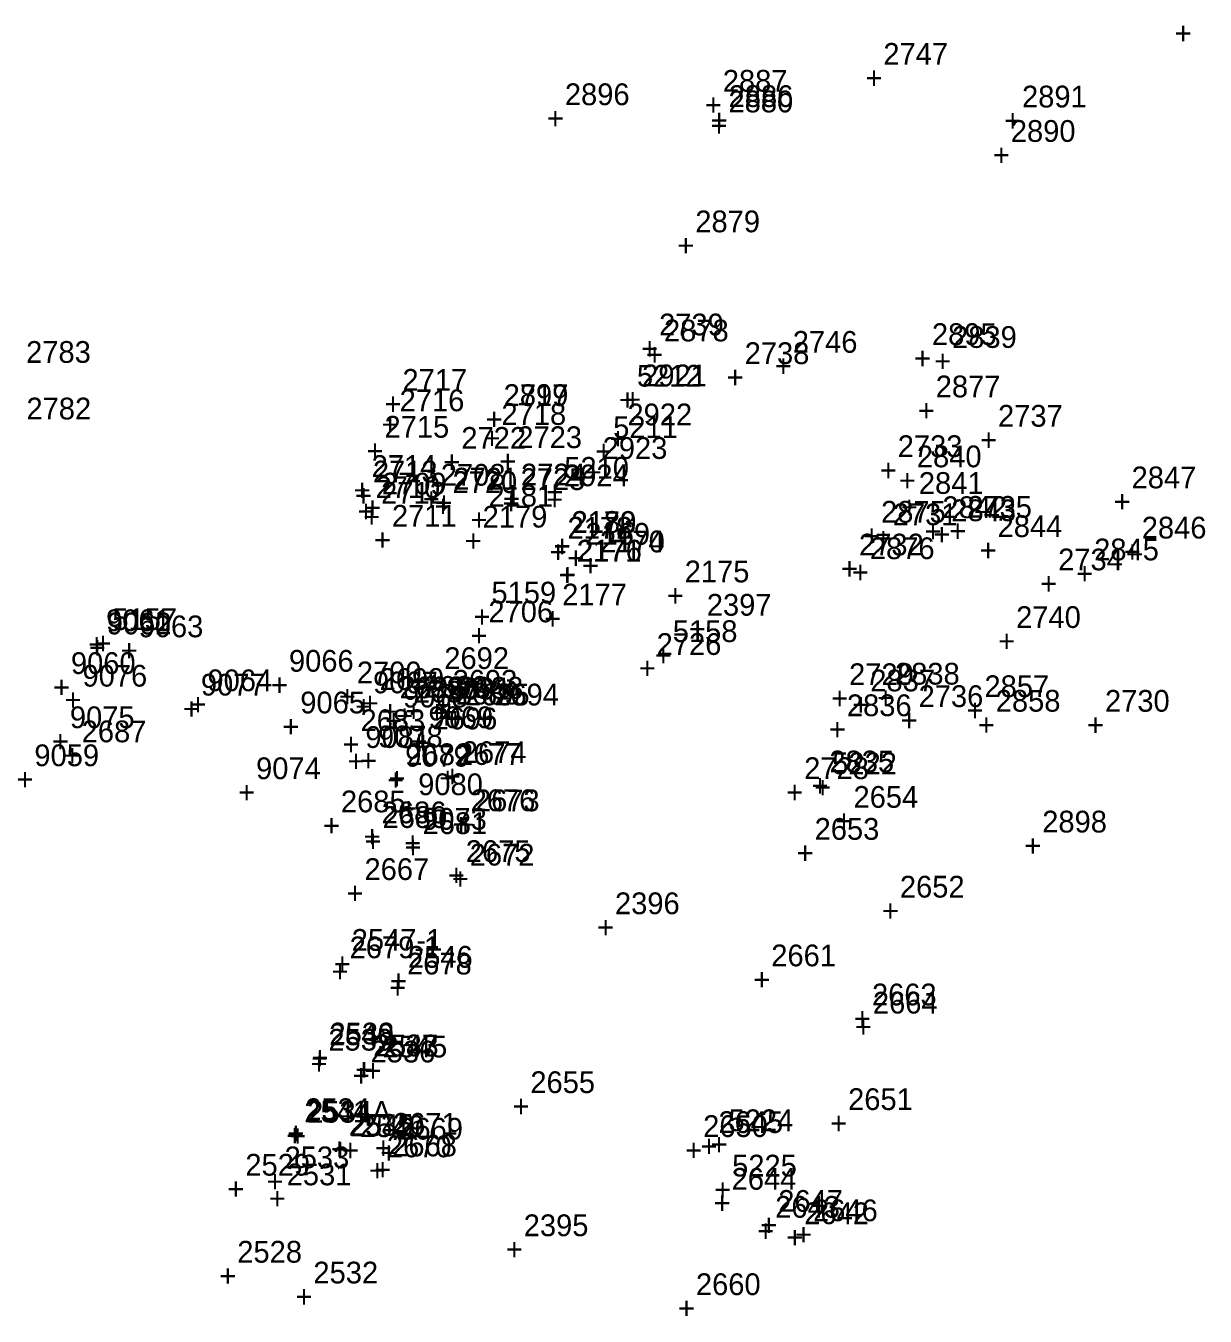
# Model space of a CAD drawing. Extents: x 1136220 to 1137808, y 528804 to 531215.
# Drawn here: x 1136907.4 to 1137043, y 529478.8 to 529627.1 of the extents above; entities that cross this region are included whole.
import ezdxf

# ---------------------------------------------------------------- set-up
doc = ezdxf.new("R2010")
doc.units = 0
for name, color, linetype in [('S_Buildings', 7, 'Continuous'), ('S_Buildings_Attachments', 7, 'Continuous'), ('S_Buildings_SillElevation', 7, 'Continuous'), ('S_Buildings_Steps_Brick', 7, 'Continuous'), ('S_Curb_Type_1', 7, 'Continuous'), ('S_Curb_Type_3', 7, 'Continuous'), ('S_Drainage_CB', 7, 'Continuous'), ('S_Drainage_Culvert_Top', 7, 'Continuous'), ('S_Drainage_Invert', 7, 'Continuous'), ('S_Drainage_Sump', 7, 'Continuous'), ('S_Ground_Elevation', 7, 'Continuous'), ('S_Ground_SpotElevation', 7, 'Continuous'), ('S_Misc_MiscItems', 7, 'Continuous'), ('S_Property_Walkways', 7, 'Continuous'), ('S_Roadway_Centerline', 7, 'Continuous'), ('S_Roadway_Drive_Paved', 7, 'Continuous'), ('S_Roadway_Edge_Pavement', 7, 'Continuous'), ('S_Roadway_Sidewalks', 7, 'Continuous'), ('S_Traffic_Sign_SinglePost', 7, 'Continuous'), ('S_Utilities_Gas_Gate', 7, 'Continuous'), ('S_Utilities_GuyWire3', 7, 'Continuous'), ('S_Utilities_Hydrant', 7, 'Continuous'), ('S_Utilities_Pole_Joint', 7, 'Continuous'), ('S_Utilities_UG_Gas_Line', 7, 'Continuous'), ('S_Utilities_UG_Sanitary_MH', 7, 'Continuous'), ('S_Utilities_UG_Water_Gate', 7, 'Continuous'), ('S_Utilities_UG_Water_Line', 7, 'Continuous')]:
    doc.layers.add(name, color=color, linetype=linetype)

msp = doc.modelspace()

# ---------------------------------------------------------------- texts
at = {"layer": 'S_Buildings'}
for s, p in [('+', (1137039.47, 529624.97)), ('2896', (1136969.39, 529617.95)), ('+', (1136967.33, 529615.2)), ('2719', (1136962.35, 529583.37)), ('2897', (1136962.35, 529583.38)), ('+', (1136960.29, 529580.63)), ('+', (1136960.28, 529580.62)), ('2687', (1136913.86, 529544.72)), ('+', (1136911.8, 529541.97)), ('2686', (1136948.33, 529535.41)), ('+', (1136946.27, 529532.66)), ('2652', (1137007.89, 529526.87)), ('+', (1137005.83, 529524.12)), ('2651', (1137001.94, 529502.45)), ('+', (1136999.88, 529499.7)), ('2533', (1136937.17, 529495.76)), ('+', (1136935.11, 529493.01))]:
    msp.add_text(s, height=2.5, dxfattribs=at).set_placement(p)
at = {"layer": 'S_Buildings_Attachments'}
for s, p in [('2547-1', (1136944.89, 529520.75)), ('2546', (1136951.36, 529518.81)), ('+', (1136942.83, 529518)), ('+', (1136949.29, 529516.06)), ('2545', (1136948.43, 529508.49)), ('+', (1136946.37, 529505.74))]:
    msp.add_text(s, height=2.5, dxfattribs=at).set_placement(p)
at = {"layer": 'S_Buildings_SillElevation'}
for s, p in [('2667', (1136946.36, 529528.89)), ('+', (1136944.29, 529526.14)), ('2664', (1137004.79, 529513.54)), ('+', (1137002.72, 529510.79))]:
    msp.add_text(s, height=2.5, dxfattribs=at).set_placement(p)
at = {"layer": 'S_Buildings_Steps_Brick'}
for s, p in [('2538', (1136942.34, 529509.99)), ('2539', (1136942.21, 529509.28)), ('2537', (1136947.37, 529508.63)), ('+', (1136940.28, 529507.24)), ('2536', (1136947.06, 529507.92)), ('+', (1136940.15, 529506.53)), ('+', (1136945.31, 529505.88)), ('+', (1136945, 529505.17)), ('2534', (1136939.55, 529501.29)), ('2534A', (1136939.77, 529501)), ('2535', (1136944.55, 529499.49)), ('+', (1136937.49, 529498.54)), ('+', (1136937.71, 529498.25)), ('+', (1136942.49, 529496.74))]:
    msp.add_text(s, height=2.5, dxfattribs=at).set_placement(p)
at = {"layer": 'S_Curb_Type_1'}
for s, p in [('5212', (1136977.67, 529585.6)), ('+', (1136975.61, 529582.85)), ('5211', (1136974.94, 529579.69)), ('+', (1136972.87, 529576.94)), ('2714', (1136947.18, 529575.22)), ('5210', (1136969.32, 529575.01)), ('2721', (1136956.57, 529573.77)), ('2724', (1136964.34, 529574.24)), ('+', (1136945.12, 529572.47)), ('+', (1136967.26, 529572.26)), ('+', (1136954.51, 529571.02)), ('+', (1136962.28, 529571.49))]:
    msp.add_text(s, height=2.5, dxfattribs=at).set_placement(p)
at = {"layer": 'S_Curb_Type_3'}
for s, p in [('9062', (1136916.74, 529557.12)), ('9063', (1136920.4, 529556.79)), ('+', (1136914.68, 529554.37)), ('+', (1136918.34, 529554.04)), ('9066', (1136937.68, 529552.83)), ('+', (1136935.62, 529550.08)), ('9067', (1136947.35, 529550.35)), ('9068', (1136950.79, 529548.72)), ('+', (1136945.29, 529547.6)), ('+', (1136948.73, 529545.97)), ('9069', (1136953.71, 529546.34)), ('+', (1136951.65, 529543.59)), ('2677', (1136957, 529542.12)), ('5222', (1137000.11, 529541.05)), ('+', (1136954.94, 529539.37)), ('+', (1136998.05, 529538.3)), ('2676', (1136958.56, 529536.8)), ('+', (1136956.5, 529534.05)), ('2675', (1136958, 529530.96)), ('+', (1136955.94, 529528.21)), ('2671', (1136949.63, 529499.61)), ('5224', (1136988.2, 529500.02)), ('+', (1136947.56, 529496.86)), ('2670', (1136948.93, 529497.02)), ('+', (1136986.14, 529497.27)), ('5225', (1136988.61, 529494.81)), ('+', (1136946.87, 529494.27)), ('+', (1136986.55, 529492.06)), ('2647', (1136993.91, 529490.75)), ('2646', (1136997.91, 529489.67)), ('+', (1136991.85, 529488)), ('+', (1136995.84, 529486.92))]:
    msp.add_text(s, height=2.5, dxfattribs=at).set_placement(p)
at = {"layer": 'S_Drainage_CB'}
for s, p in [('2709', (1136948.36, 529573.2)), ('+', (1136946.3, 529570.45)), ('2688', (1136957.17, 529549.73)), ('+', (1136955.11, 529546.98))]:
    msp.add_text(s, height=2.5, dxfattribs=at).set_placement(p)
at = {"layer": 'S_Drainage_Culvert_Top'}
for s, p in [('2181', (1136960.61, 529571.81)), ('2711', (1136949.51, 529569.5)), ('2179', (1136959.94, 529569.4)), ('2180', (1136970.16, 529568.79)), ('+', (1136958.55, 529569.06)), ('2178', (1136969.68, 529568.11)), ('+', (1136947.45, 529566.75)), ('+', (1136957.88, 529566.65)), ('2174', (1136973.42, 529566.55)), ('+', (1136967.62, 529565.36)), ('+', (1136968.1, 529566.04)), ('2176', (1136970.8, 529565.5)), ('+', (1136971.36, 529563.8)), ('2175', (1136983.16, 529563.1)), ('+', (1136968.74, 529562.75)), ('2177', (1136969.08, 529560.45)), ('+', (1136981.1, 529560.35)), ('+', (1136967.01, 529557.7)), ('2692', (1136955.53, 529553.14)), ('2690', (1136953.1, 529549.83)), ('+', (1136953.47, 529550.39)), ('2694', (1136961.27, 529548.95)), ('+', (1136951.04, 529547.08)), ('+', (1136959.21, 529546.2))]:
    msp.add_text(s, height=2.5, dxfattribs=at).set_placement(p)
at = {"layer": 'S_Drainage_Invert'}
for s, p in [('2712', (1136948.27, 529572.15)), ('+', (1136946.21, 529569.4)), ('2173', (1136970.14, 529568.76)), ('2172', (1136969.72, 529568.13)), ('2170', (1136973.44, 529566.55)), ('+', (1136967.66, 529565.38)), ('+', (1136968.08, 529566.01)), ('2171', (1136970.74, 529565.46)), ('+', (1136971.38, 529563.8)), ('+', (1136968.68, 529562.71)), ('2691', (1136955.78, 529549.63)), ('2693', (1136956.49, 529550.54)), ('2695', (1136957.89, 529548.96)), ('+', (1136954.43, 529547.79)), ('+', (1136953.72, 529546.88)), ('+', (1136955.83, 529546.21))]:
    msp.add_text(s, height=2.5, dxfattribs=at).set_placement(p)
at = {"layer": 'S_Drainage_Sump'}
for s, p in [('2710', (1136947.63, 529572.78)), ('+', (1136945.57, 529570.03)), ('2689', (1136956.85, 529549.06)), ('+', (1136954.79, 529546.31))]:
    msp.add_text(s, height=2.5, dxfattribs=at).set_placement(p)
at = {"layer": 'S_Ground_Elevation'}
for s, p in [('2887', (1136987.54, 529619.5)), ('2886', (1136988.21, 529617.74)), ('+', (1136985.48, 529616.75)), ('+', (1136986.15, 529614.99)), ('9076', (1136913.95, 529551.12)), ('9077', (1136927.56, 529550.09)), ('+', (1136911.89, 529548.37)), ('+', (1136925.5, 529547.34)), ('9075', (1136912.5, 529546.34)), ('9078', (1136947.91, 529544.14)), ('+', (1136910.44, 529543.59)), ('+', (1136945.84, 529541.39)), ('9079', (1136951.03, 529541.92)), ('9074', (1136933.9, 529540.48)), ('+', (1136948.97, 529539.17)), ('9080', (1136952.53, 529538.64)), ('+', (1136931.84, 529537.73)), ('+', (1136950.47, 529535.89)), ('9073', (1136952.98, 529534.67)), ('+', (1136950.92, 529531.92)), ('2540', (1136942.29, 529509.9)), ('2543', (1136947.44, 529508.62)), ('+', (1136940.23, 529507.15)), ('+', (1136945.38, 529505.87)), ('2541', (1136939.44, 529501.04)), ('2542', (1136944.67, 529499.44)), ('+', (1136937.38, 529498.29)), ('+', (1136942.61, 529496.69))]:
    msp.add_text(s, height=2.5, dxfattribs=at).set_placement(p)
at = {"layer": 'S_Ground_SpotElevation'}
for s, p in [('2717', (1136950.72, 529585.12)), ('2716', (1136950.4, 529582.77)), ('+', (1136948.66, 529582.37)), ('2718', (1136962.1, 529581.2)), ('+', (1136948.34, 529580.02)), ('+', (1136960.04, 529578.45)), ('2685', (1136943.65, 529536.67)), ('+', (1136941.59, 529533.92)), ('2663', (1137004.68, 529514.48)), ('+', (1137002.61, 529511.73)), ('2660', (1136984.45, 529481.18)), ('+', (1136982.39, 529478.44))]:
    msp.add_text(s, height=2.5, dxfattribs=at).set_placement(p)
at = {"layer": 'S_Misc_MiscItems'}
for s, p in [('2898', (1137024.25, 529534.35)), ('+', (1137022.19, 529531.6))]:
    msp.add_text(s, height=2.5, dxfattribs=at).set_placement(p)
at = {"layer": 'S_Property_Walkways'}
for s, p in [('2715', (1136948.66, 529579.73)), ('2722', (1136957.49, 529578.45)), ('2723', (1136963.92, 529578.53)), ('+', (1136946.6, 529576.98)), ('+', (1136955.42, 529575.7)), ('+', (1136961.86, 529575.78)), ('2683', (1136945.9, 529546)), ('+', (1136943.84, 529543.25)), ('2682', (1136951.18, 529542.09)), ('+', (1136949.12, 529539.34)), ('2680', (1136948.43, 529534.87)), ('2681', (1136953.03, 529534.17)), ('+', (1136946.37, 529532.12)), ('+', (1136950.96, 529531.42)), ('2679-1', (1136944.65, 529519.9)), ('2678', (1136951.25, 529518.03)), ('+', (1136942.58, 529517.15)), ('+', (1136949.19, 529515.28)), ('2549', (1136945.83, 529499.34)), ('+', (1136943.77, 529496.59))]:
    msp.add_text(s, height=2.5, dxfattribs=at).set_placement(p)
at = {"layer": 'S_Roadway_Centerline'}
for s, p in [('2747', (1137005.99, 529622.59)), ('+', (1137003.93, 529619.84)), ('2746', (1136995.58, 529589.49)), ('+', (1136993.51, 529586.74)), ('5159', (1136960.95, 529560.67)), ('2397', (1136985.7, 529559.27)), ('+', (1136958.89, 529557.92)), ('2740', (1137021.25, 529557.86)), ('5158', (1136981.79, 529556.24)), ('+', (1136983.64, 529556.52)), ('+', (1137019.19, 529555.11)), ('+', (1136979.73, 529553.49)), ('2396', (1136975.15, 529524.96)), ('+', (1136973.09, 529522.21)), ('2395', (1136964.66, 529487.95)), ('+', (1136962.6, 529485.2))]:
    msp.add_text(s, height=2.5, dxfattribs=at).set_placement(p)
at = {"layer": 'S_Roadway_Drive_Paved'}
for s, p in [('9061', (1136916.66, 529557.49)), ('+', (1136914.6, 529554.74)), ('9060', (1136912.62, 529552.57)), ('+', (1136910.56, 529549.82)), ('9059', (1136908.42, 529541.97)), ('+', (1136906.36, 529539.22)), ('2529', (1136932.67, 529494.91)), ('2531', (1136937.42, 529493.8)), ('+', (1136930.6, 529492.16)), ('+', (1136935.36, 529491.05)), ('2528', (1136931.74, 529484.91)), ('+', (1136929.68, 529482.16)), ('2532', (1136940.49, 529482.52)), ('+', (1136938.43, 529479.77))]:
    msp.add_text(s, height=2.5, dxfattribs=at).set_placement(p)
at = {"layer": 'S_Roadway_Edge_Pavement'}
for s, p in [('2891', (1137021.93, 529617.69)), ('2880', (1136988.19, 529617.12)), ('+', (1136986.13, 529614.37)), ('+', (1137019.87, 529614.94)), ('2890', (1137020.64, 529613.73)), ('+', (1137018.58, 529610.98)), ('2879', (1136984.38, 529603.34)), ('+', (1136982.32, 529600.59)), ('2878', (1136980.78, 529590.8)), ('2839', (1137013.89, 529590.05)), ('+', (1136978.72, 529588.05)), ('+', (1137011.83, 529587.3)), ('2921', (1136978.27, 529585.64)), ('2877', (1137012.01, 529584.37)), ('+', (1136976.21, 529582.89)), ('2922', (1136976.58, 529581.15)), ('+', (1137009.95, 529581.62)), ('+', (1136974.52, 529578.4)), ('2923', (1136973.73, 529577.29)), ('2840', (1137009.84, 529576.33)), ('2713', (1136947.33, 529574.59)), ('2720', (1136956.47, 529573.37)), ('2725', (1136964.3, 529573.71)), ('2924', (1136969.29, 529574.15)), ('+', (1136971.67, 529574.54)), ('2841', (1137010.07, 529573.27)), ('2847', (1137034.52, 529573.91)), ('+', (1137007.78, 529573.58)), ('+', (1136945.27, 529571.84)), ('+', (1136962.24, 529570.96)), ('+', (1136967.23, 529571.4)), ('2842', (1137012.78, 529570.49)), ('+', (1137032.46, 529571.16)), ('+', (1136954.41, 529570.62)), ('+', (1137008.01, 529570.52)), ('2843', (1137013.8, 529570.13)), ('+', (1137010.71, 529567.74)), ('2844', (1137019.12, 529568.31)), ('2846', (1137035.69, 529568.14)), ('+', (1137011.74, 529567.38)), ('+', (1137017.06, 529565.56)), ('2845', (1137030.22, 529565.63)), ('+', (1137033.63, 529565.39)), ('+', (1137028.16, 529562.88)), ('5157', (1136917.38, 529557.62)), ('+', (1136915.32, 529554.87)), ('2700', (1136945.48, 529551.5)), ('2838', (1137007.33, 529551.35)), ('2699', (1136948.09, 529550.74)), ('2698', (1136950.4, 529549.78)), ('2837', (1137004.49, 529550.57)), ('+', (1136943.42, 529548.75)), ('2697', (1136952.06, 529549.28)), ('+', (1137005.27, 529548.6)), ('2858', (1137018.91, 529548.24)), ('+', (1136946.03, 529547.99)), ('+', (1136948.34, 529547.03)), ('2836', (1137001.8, 529547.72)), ('+', (1137002.43, 529547.82)), ('+', (1136950, 529546.53)), ('2696', (1136954.19, 529546.2)), ('+', (1137016.85, 529545.49)), ('+', (1136999.74, 529544.97)), ('+', (1136952.13, 529543.45)), ('2674', (1136957.54, 529542.33)), ('2835', (1136999.79, 529541.26)), ('+', (1136955.48, 529539.58)), ('+', (1136997.73, 529538.51)), ('2673', (1136959.05, 529536.79)), ('+', (1136956.99, 529534.04)), ('2672', (1136958.46, 529530.55)), ('+', (1136956.4, 529527.8)), ('2661', (1136993.11, 529518.97)), ('+', (1136991.05, 529516.22)), ('2669', (1136950.24, 529499.05)), ('2645', (1136987.04, 529499.81)), ('2668', (1136949.54, 529497.13)), ('+', (1136984.98, 529497.06)), ('+', (1136948.18, 529496.3)), ('+', (1136947.48, 529494.38)), ('2644', (1136988.55, 529493.29)), ('+', (1136986.49, 529490.54)), ('2643', (1136993.56, 529490.07)), ('2642', (1136996.9, 529489.33)), ('+', (1136991.5, 529487.32)), ('+', (1136994.84, 529486.58))]:
    msp.add_text(s, height=2.5, dxfattribs=at).set_placement(p)
at = {"layer": 'S_Roadway_Sidewalks'}
for s, p in [('9064', (1136928.31, 529550.59)), ('9065', (1136938.98, 529548.04)), ('+', (1136926.25, 529547.84)), ('+', (1136936.92, 529545.3))]:
    msp.add_text(s, height=2.5, dxfattribs=at).set_placement(p)
at = {"layer": 'S_Traffic_Sign_SinglePost'}
for s, p in [('2739', (1136980.22, 529591.49)), ('+', (1136978.15, 529588.74)), ('2735', (1137015.63, 529570.52)), ('+', (1137013.57, 529567.77)), ('2736', (1137010.04, 529548.77)), ('+', (1137007.98, 529546.02)), ('9081', (1136946.46, 529544.07)), ('+', (1136944.4, 529541.32)), ('2653', (1136998.09, 529533.51)), ('+', (1136996.03, 529530.76))]:
    msp.add_text(s, height=2.5, dxfattribs=at).set_placement(p)
at = {"layer": 'S_Utilities_Gas_Gate'}
for s, p in [('2731', (1137007.07, 529569.67)), ('2732', (1137003.19, 529566.19)), ('+', (1137005.01, 529566.92)), ('+', (1137001.13, 529563.44)), ('2650', (1136985.28, 529499.35)), ('+', (1136983.22, 529496.6))]:
    msp.add_text(s, height=2.5, dxfattribs=at).set_placement(p)
at = {"layer": 'S_Utilities_GuyWire3'}
msp.add_text('2783', height=2.5, dxfattribs=at).set_placement((1136907.47, 529588.33))
at = {"layer": 'S_Utilities_Hydrant'}
for s, p in [('2737', (1137019.17, 529580.99)), ('+', (1137017.11, 529578.24))]:
    msp.add_text(s, height=2.5, dxfattribs=at).set_placement(p)
at = {"layer": 'S_Utilities_Pole_Joint'}
for s, p in [('2782', (1136907.51, 529581.83)), ('2654', (1137002.56, 529537.19)), ('+', (1137000.5, 529534.44))]:
    msp.add_text(s, height=2.5, dxfattribs=at).set_placement(p)
at = {"layer": 'S_Utilities_UG_Gas_Line'}
for s, p in [('2895', (1137011.57, 529590.38)), ('+', (1137009.51, 529587.63)), ('2733', (1137007.64, 529577.5)), ('+', (1137005.58, 529574.75)), ('2875', (1137005.73, 529569.96)), ('+', (1137003.67, 529567.21)), ('2876', (1137004.44, 529565.77)), ('2734', (1137026.08, 529564.48)), ('+', (1137002.38, 529563.02)), ('+', (1137024.02, 529561.73)), ('2728', (1136996.89, 529540.49)), ('+', (1136994.83, 529537.74))]:
    msp.add_text(s, height=2.5, dxfattribs=at).set_placement(p)
at = {"layer": 'S_Utilities_UG_Sanitary_MH'}
for s, p in [('2169', (1136971.74, 529567.43)), ('+', (1136969.67, 529564.68))]:
    msp.add_text(s, height=2.5, dxfattribs=at).set_placement(p)
at = {"layer": 'S_Utilities_UG_Water_Gate'}
for s, p in [('2738', (1136990.05, 529588.19)), ('+', (1136987.99, 529585.44)), ('2708', (1136955.13, 529574.21)), ('+', (1136953.07, 529571.46)), ('2706', (1136960.6, 529558.51)), ('+', (1136958.54, 529555.76)), ('2655', (1136965.42, 529504.4)), ('+', (1136963.36, 529501.65))]:
    msp.add_text(s, height=2.5, dxfattribs=at).set_placement(p)
at = {"layer": 'S_Utilities_UG_Water_Line'}
for s, p in [('2726', (1136979.94, 529554.76)), ('+', (1136977.88, 529552.01)), ('2729', (1137002.05, 529551.29)), ('2857', (1137017.61, 529549.91)), ('+', (1136999.99, 529548.54)), ('2730', (1137031.46, 529548.23)), ('+', (1137015.54, 529547.16)), ('+', (1137029.4, 529545.48))]:
    msp.add_text(s, height=2.5, dxfattribs=at).set_placement(p)

doc.saveas('drawing.dxf')
